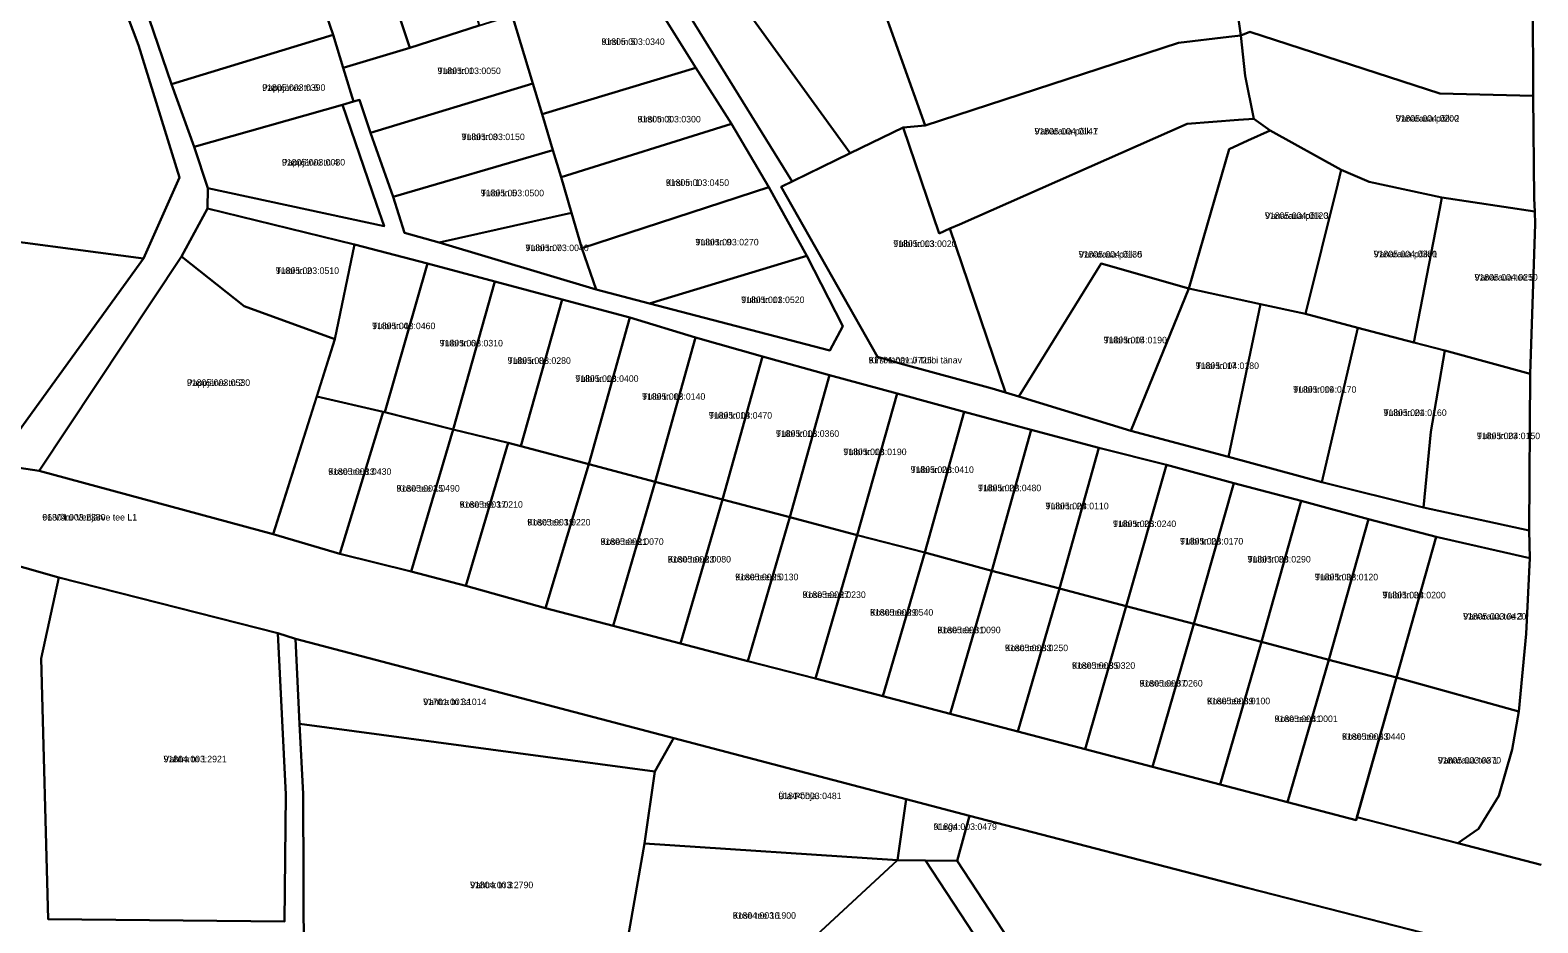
# Model space of a CAD drawing. Extents: x 655954 to 711923, y 6395079 to 6429745.
# Drawn here: x 680345.2 to 680691.2, y 6412086.7 to 6412291.4 of the extents above; entities that cross this region are included whole.
import ezdxf

# ---------------------------------------------------------------- set-up
doc = ezdxf.new("R2010")
doc.units = 0
for name, color, linetype in [('L_AADRESS', 7, 'Continuous'), ('PIIR', 7, 'Continuous'), ('TUNNUS', 7, 'Continuous')]:
    doc.layers.add(name, color=color, linetype=linetype)

msp = doc.modelspace()

# ---------------------------------------------------------------- linework, layer by layer
at = {"layer": 'PIIR'}
for points in [[(680691.94, 6412100.04), (680672.88, 6412104.96), (680677.62, 6412108.25), (680682.23, 6412115.86), (680685.31, 6412126.44), (680686.83, 6412135.18), (680688.5, 6412152.96), (680689.33, 6412170.32), (680689.19, 6412176.7), (680689.48, 6412212.64), (680690.62, 6412246.92), (680690.49, 6412249.87), (680690.36, 6412252.83), (680690.15, 6412276.38), (680690.04, 6412298.6), (680689.21, 6412320.29), (680688.26, 6412343.55), (680687.16, 6412365.36), (680684.23, 6412414.79), (680682.22, 6412435.76), (680657.8, 6412581.77), (680647.63, 6412619.14), (680636.79, 6412656.6), (680630.27, 6412681.69)], [(680468.27, 6412340.52), (680520.07, 6412256.74), (680517.59, 6412255.53), (680539.7, 6412216.49), (680544.84, 6412214.98), (680565.96, 6412209.26), (680569.03, 6412208.35), (680572.07, 6412207.45), (680597.84, 6412199.56), (680620.24, 6412193.6), (680641.67, 6412187.79), (680664.99, 6412181.96), (680689.19, 6412176.7), (680689.33, 6412170.32), (680667.84, 6412175.24), (680652.34, 6412179.26), (680636.92, 6412183.46), (680621.43, 6412187.52), (680606.01, 6412191.72), (680590.49, 6412195.64), (680574.95, 6412199.75), (680559.57, 6412203.92), (680544.16, 6412208.15), (680528.66, 6412212.34), (680513.3, 6412216.63), (680497.9, 6412220.95), (680482.82, 6412225.53), (680467.33, 6412229.65), (680451.85, 6412233.8), (680436.43, 6412237.95), (680419.64, 6412242.31), (680385.97, 6412250.53), (680386, 6412255.23), (680422.59, 6412247.31), (680426.51, 6412246.46), (680424.75, 6412251.56), (680416.9, 6412274.33), (680419.47, 6412275.06), (680420.82, 6412275.45), (680423.36, 6412267.88), (680428.53, 6412253.22), (680431.1, 6412244.93), (680439.08, 6412242.76), (680475.1, 6412232), (680487.39, 6412228.72), (680528.7, 6412218.01), (680531.74, 6412223.58), (680523.46, 6412239.68), (680514.72, 6412255.44), (680506.14, 6412269.96), (680498.01, 6412282.81), (680484.86, 6412303.92)], [(680372.55, 6412294.06), (680377.69, 6412279.06), (680382.91, 6412264.69), (680386, 6412255.23), (680385.97, 6412250.53), (680379.93, 6412239.55), (680347.28, 6412190.34), (680337.05, 6412191.89), (680371.24, 6412239.08), (680379.49, 6412257.67), (680370.12, 6412288.02), (680357.48, 6412321.49)], [(680705.81, 6412074.78), (680677.03, 6412081.28), (680624.53, 6412094.76), (680560.78, 6412111.23), (680546.23, 6412115.07), (680492.93, 6412129.05), (680406.11, 6412151.85), (680402.06, 6412153.11), (680351.83, 6412165.88), (680336.14, 6412170.36), (680242.17, 6412197.84), (680196.94, 6412209.71), (680171.26, 6412215.95), (680148.41, 6412221.98), (680121.74, 6412229.75), (680098.7, 6412238.99)], [(680337.05, 6412191.89), (680347.28, 6412190.34), (680400.99, 6412175.85), (680416.33, 6412171.33), (680432.63, 6412167.26), (680445.22, 6412163.97), (680463.53, 6412158.9), (680479, 6412154.86), (680494.47, 6412150.81), (680509.95, 6412146.76), (680525.42, 6412142.71), (680540.9, 6412138.67), (680556.38, 6412134.62), (680571.85, 6412130.57), (680587.32, 6412126.52), (680602.8, 6412122.48), (680618.27, 6412118.43), (680633.75, 6412114.38), (680649.5, 6412110.26), (680649.69, 6412110.94), (680672.88, 6412104.96), (680691.94, 6412100.04)], [(680340.18, 6412080.79), (680339.82, 6412121.56), (680338.98, 6412165.98), (680336.14, 6412170.36), (680351.83, 6412165.88), (680347.79, 6412147.37), (680349.36, 6412087.58), (680403.59, 6412086.99), (680403.88, 6412116.18), (680402.06, 6412153.11), (680406.11, 6412151.85), (680407.08, 6412132.37), (680407.88, 6412116.26), (680408.14, 6412056.92)]]:
    msp.add_lwpolyline(points, dxfattribs=at)
for points in [[(680468.27, 6412340.52), (680486.71, 6412324.31), (680504.21, 6412303.58), (680533.37, 6412263.23), (680520.07, 6412256.74)], [(680419.26, 6412326.61), (680436.31, 6412331.9), (680448.28, 6412292.55), (680432.38, 6412287.38)], [(680417.09, 6412282.78), (680414.79, 6412290.36), (680409.59, 6412305.53), (680404.56, 6412321.9), (680419.26, 6412326.61), (680432.38, 6412287.38)], [(680270.91, 6412285.97), (680269.56, 6412291.77), (680268.21, 6412300.15), (680272.04, 6412300.46), (680309.99, 6412309.75), (680357.48, 6412321.49), (680370.12, 6412288.02), (680379.49, 6412257.67), (680371.24, 6412239.08), (680328.42, 6412244.77), (680267.41, 6412253.09), (680266.95, 6412257.92), (680268.29, 6412258.95), (680268.5, 6412260.8), (680268.26, 6412264.21), (680268.94, 6412267.94), (680271.87, 6412272.08), (680272.87, 6412275.64), (680272.53, 6412278.95)], [(680618.32, 6412308.62), (680620.58, 6412307.34), (680623.03, 6412290.2), (680620.29, 6412289.89), (680608.75, 6412288.56), (680550.62, 6412269.6), (680539.47, 6412300.88), (680536.7, 6412308.12), (680581.04, 6412320.56), (680588.15, 6412306.97), (680590.63, 6412307.28)], [(680504.21, 6412303.58), (680533.53, 6412316.71), (680536.7, 6412308.12), (680539.47, 6412300.88), (680550.62, 6412269.6), (680545.58, 6412269.1), (680533.37, 6412263.23)], [(680377.69, 6412279.06), (680372.55, 6412294.06), (680409.59, 6412305.53), (680414.79, 6412290.36)], [(680667.16, 6412298.96), (680690.04, 6412298.6), (680690.15, 6412276.38), (680668.68, 6412276.91), (680625.09, 6412291.05), (680623.03, 6412290.2), (680620.58, 6412307.34), (680622.84, 6412306.06)], [(680498.01, 6412282.81), (680462.72, 6412272.18), (680460.59, 6412279.24), (680455.87, 6412294.86), (680463.42, 6412297.01), (680484.86, 6412303.92)], [(680420.82, 6412275.45), (680419.47, 6412275.06), (680417.09, 6412282.78), (680432.38, 6412287.38), (680448.28, 6412292.55), (680455.87, 6412294.86), (680460.59, 6412279.24), (680423.36, 6412267.88)], [(680625.09, 6412291.05), (680668.68, 6412276.91), (680690.15, 6412276.38), (680690.36, 6412252.83), (680690.49, 6412249.87), (680669.19, 6412253.04), (680652.49, 6412256.69), (680646.06, 6412259.42), (680629.76, 6412268.41), (680626.03, 6412271.13), (680624.08, 6412280.94), (680623.03, 6412290.2)], [(680414.79, 6412290.36), (680417.09, 6412282.78), (680419.47, 6412275.06), (680416.9, 6412274.33), (680382.91, 6412264.69), (680377.69, 6412279.06)], [(680553.84, 6412244.84), (680545.58, 6412269.1), (680550.62, 6412269.6), (680608.75, 6412288.56), (680620.3, 6412289.88), (680623.03, 6412290.2), (680624.08, 6412280.94), (680626.03, 6412271.13), (680622.48, 6412270.85), (680610.75, 6412269.93), (680558.47, 6412246.88), (680556.28, 6412245.92)], [(680498.01, 6412282.81), (680506.14, 6412269.96), (680467.07, 6412257.75), (680465.21, 6412263.92), (680462.72, 6412272.18)], [(680460.59, 6412279.24), (680462.72, 6412272.18), (680465.21, 6412263.92), (680428.53, 6412253.22), (680423.36, 6412267.88)], [(680382.91, 6412264.69), (680416.9, 6412274.33), (680424.75, 6412251.56), (680426.51, 6412246.46), (680422.59, 6412247.31), (680386, 6412255.23)], [(680626.03, 6412271.13), (680629.76, 6412268.41), (680624.68, 6412266.13), (680620.36, 6412264.18), (680611.12, 6412232.19), (680590.98, 6412237.95), (680572.07, 6412207.45), (680569.03, 6412208.35), (680556.28, 6412245.92), (680558.47, 6412246.88), (680610.75, 6412269.93), (680622.48, 6412270.85)], [(680506.14, 6412269.96), (680514.72, 6412255.44), (680471.82, 6412241.48), (680469.46, 6412249.54), (680467.07, 6412257.75)], [(680553.84, 6412244.84), (680556.28, 6412245.92), (680569.03, 6412208.35), (680565.96, 6412209.26), (680544.84, 6412214.98), (680539.7, 6412216.49), (680517.59, 6412255.53), (680533.37, 6412263.23), (680545.58, 6412269.1)], [(680629.76, 6412268.41), (680646.06, 6412259.42), (680645.27, 6412256.23), (680637.89, 6412226.37), (680627.58, 6412228.64), (680611.12, 6412232.19), (680620.36, 6412264.18), (680624.68, 6412266.13)], [(680465.21, 6412263.92), (680467.07, 6412257.75), (680469.46, 6412249.54), (680439.08, 6412242.76), (680431.1, 6412244.93), (680428.53, 6412253.22)], [(680266.95, 6412257.92), (680267.41, 6412253.09), (680328.42, 6412244.77), (680371.24, 6412239.08), (680337.05, 6412191.89), (680190.32, 6412232.69), (680191.57, 6412236.5), (680194.23, 6412244.67), (680196.86, 6412252.6), (680212.46, 6412248.67), (680230.28, 6412253.54), (680253.6, 6412257.24), (680261.5, 6412255.76)], [(680668.71, 6412250.56), (680662.72, 6412219.81), (680649.9, 6412223.21), (680637.89, 6412226.37), (680645.27, 6412256.23), (680646.06, 6412259.42), (680652.49, 6412256.69), (680669.19, 6412253.04)], [(680514.72, 6412255.44), (680523.46, 6412239.68), (680487.39, 6412228.72), (680475.1, 6412232), (680471.82, 6412241.48)], [(680669.19, 6412253.04), (680690.49, 6412249.87), (680690.62, 6412246.92), (680689.48, 6412212.64), (680669.89, 6412217.97), (680662.73, 6412219.81), (680668.71, 6412250.56)], [(680394.31, 6412228.15), (680379.93, 6412239.55), (680385.97, 6412250.53), (680419.64, 6412242.31), (680415.16, 6412220.56)], [(680469.46, 6412249.54), (680471.82, 6412241.48), (680475.1, 6412232), (680439.08, 6412242.76)], [(680379.93, 6412239.55), (680394.31, 6412228.15), (680415.15, 6412220.55), (680400.99, 6412175.85), (680347.28, 6412190.34)], [(680426.26, 6412203.91), (680411, 6412207.4), (680415.16, 6412220.56), (680419.64, 6412242.31), (680436.43, 6412237.95), (680426.59, 6412203.83)], [(680523.46, 6412239.68), (680531.74, 6412223.58), (680528.7, 6412218.01), (680487.39, 6412228.72)], [(680442.29, 6412199.83), (680426.59, 6412203.83), (680436.43, 6412237.95), (680451.85, 6412233.8)], [(680572.07, 6412207.45), (680590.98, 6412237.95), (680611.12, 6412232.19), (680597.84, 6412199.56)], [(680467.33, 6412229.65), (680457.86, 6412196.01), (680454.95, 6412196.78), (680442.29, 6412199.83), (680451.85, 6412233.8)], [(680597.84, 6412199.56), (680611.12, 6412232.19), (680627.58, 6412228.64), (680620.24, 6412193.6)], [(680473.43, 6412191.9), (680457.86, 6412196.01), (680467.33, 6412229.65), (680482.82, 6412225.53)], [(680488.69, 6412187.87), (680473.43, 6412191.9), (680482.82, 6412225.53), (680497.9, 6412220.95)], [(680620.24, 6412193.6), (680627.58, 6412228.64), (680637.89, 6412226.37), (680649.9, 6412223.21), (680641.67, 6412187.79)], [(680641.67, 6412187.79), (680649.9, 6412223.21), (680662.72, 6412219.81), (680669.89, 6412217.97), (680666.68, 6412199.35), (680664.99, 6412181.96)], [(680497.9, 6412220.95), (680513.3, 6412216.63), (680504.09, 6412183.81), (680488.69, 6412187.87)], [(680513.3, 6412216.63), (680528.66, 6412212.34), (680519.55, 6412179.73), (680504.09, 6412183.81)], [(680666.68, 6412199.35), (680669.89, 6412217.97), (680689.48, 6412212.64), (680689.19, 6412176.7), (680664.99, 6412181.96)], [(680544.16, 6412208.15), (680535.01, 6412175.64), (680519.55, 6412179.73), (680528.66, 6412212.34)], [(680544.16, 6412208.15), (680559.57, 6412203.92), (680550.52, 6412171.66), (680535.01, 6412175.64)], [(680411, 6412207.4), (680426.26, 6412203.91), (680416.33, 6412171.33), (680400.99, 6412175.85)], [(680426.26, 6412203.91), (680442.29, 6412199.83), (680432.63, 6412167.26), (680416.33, 6412171.33)], [(680574.95, 6412199.75), (680565.95, 6412167.47), (680550.52, 6412171.66), (680559.57, 6412203.92)], [(680442.29, 6412199.83), (680454.95, 6412196.78), (680445.22, 6412163.97), (680432.63, 6412167.26)], [(680590.49, 6412195.64), (680581.44, 6412163.39), (680565.95, 6412167.47), (680574.95, 6412199.75)], [(680454.95, 6412196.78), (680457.86, 6412196.01), (680473.43, 6412191.9), (680463.53, 6412158.9), (680445.22, 6412163.97)], [(680590.49, 6412195.64), (680606.01, 6412191.72), (680596.77, 6412159.33), (680581.44, 6412163.39)], [(680473.43, 6412191.9), (680488.69, 6412187.87), (680479, 6412154.86), (680463.53, 6412158.9)], [(680606.01, 6412191.72), (680621.43, 6412187.52), (680612.25, 6412155.26), (680596.77, 6412159.33)], [(680488.69, 6412187.87), (680504.09, 6412183.81), (680494.47, 6412150.81), (680479, 6412154.86)], [(680636.92, 6412183.46), (680627.76, 6412151.16), (680612.25, 6412155.26), (680621.43, 6412187.52)], [(680504.09, 6412183.81), (680519.55, 6412179.73), (680509.95, 6412146.76), (680494.47, 6412150.81)], [(680636.92, 6412183.46), (680652.34, 6412179.26), (680643.28, 6412147.06), (680627.76, 6412151.16)], [(680519.55, 6412179.73), (680535.01, 6412175.64), (680525.42, 6412142.71), (680509.95, 6412146.76)], [(680652.34, 6412179.26), (680667.84, 6412175.24), (680658.78, 6412142.98), (680643.28, 6412147.06)], [(680535.01, 6412175.64), (680550.52, 6412171.66), (680540.9, 6412138.67), (680525.42, 6412142.71)], [(680689.33, 6412170.32), (680688.5, 6412152.96), (680686.83, 6412135.18), (680658.78, 6412142.98), (680667.84, 6412175.24)], [(680550.52, 6412171.66), (680565.95, 6412167.47), (680556.38, 6412134.62), (680540.9, 6412138.67)], [(680565.95, 6412167.47), (680581.44, 6412163.39), (680571.85, 6412130.57), (680556.38, 6412134.62)], [(680347.79, 6412147.37), (680351.83, 6412165.88), (680402.06, 6412153.11), (680403.88, 6412116.18), (680403.59, 6412086.99), (680349.36, 6412087.58)], [(680581.44, 6412163.39), (680596.77, 6412159.33), (680587.32, 6412126.52), (680571.85, 6412130.57)], [(680596.77, 6412159.33), (680612.25, 6412155.26), (680602.8, 6412122.48), (680587.32, 6412126.52)], [(680612.25, 6412155.26), (680627.76, 6412151.16), (680618.27, 6412118.43), (680602.8, 6412122.48)], [(680492.67, 6412128.6), (680488.61, 6412121.45), (680407.08, 6412132.37), (680406.11, 6412151.85), (680492.93, 6412129.05)], [(680627.76, 6412151.16), (680643.28, 6412147.06), (680633.75, 6412114.38), (680618.27, 6412118.43)], [(680643.28, 6412147.06), (680658.78, 6412142.98), (680649.5, 6412110.26), (680633.75, 6412114.38)], [(680685.31, 6412126.44), (680682.23, 6412115.86), (680677.62, 6412108.25), (680672.88, 6412104.96), (680649.69, 6412110.94), (680658.78, 6412142.98), (680686.83, 6412135.18)], [(680431.81, 6412061.43), (680408.14, 6412056.92), (680407.88, 6412116.26), (680407.08, 6412132.37), (680488.61, 6412121.45), (680486.18, 6412104.9), (680481.38, 6412077.45), (680480.42, 6412070.77)], [(680492.67, 6412128.6), (680492.93, 6412129.05), (680546.23, 6412115.07), (680544.25, 6412101.11), (680486.18, 6412104.9), (680488.61, 6412121.45)], [(680546.23, 6412115.07), (680560.78, 6412111.23), (680557.95, 6412100.96), (680550.71, 6412101.04), (680544.25, 6412101.11)], [(680677.03, 6412081.28), (680685.71, 6412071.64), (680689.23, 6412054.08), (680672.6, 6412046.64), (680620.2, 6412023.18), (680611.8, 6412018.81), (680557.95, 6412100.96), (680560.78, 6412111.23), (680624.53, 6412094.76)], [(680486.18, 6412104.9), (680544.25, 6412101.11), (680511.18, 6412070.4), (680481.38, 6412077.45)], [(680544.25, 6412101.11), (680550.71, 6412101.04), (680580.77, 6412055.2), (680552.21, 6412022.55), (680551.29, 6412021.49), (680549.92, 6412023.92), (680548.09, 6412023.97), (680546.58, 6412025.26), (680546.91, 6412029.19), (680546.21, 6412031.37), (680544.02, 6412034.93), (680542.63, 6412038.58), (680538.09, 6412047.02), (680530.02, 6412054.64), (680526.3, 6412058.97), (680512.15, 6412067.76), (680509.19, 6412068.44), (680511.18, 6412070.4)], [(680550.71, 6412101.04), (680557.95, 6412100.96), (680611.8, 6412018.81), (680604.05, 6411974.9), (680595.49, 6411963.69), (680594.02, 6411961.84), (680593.2, 6411962.5), (680587.62, 6411966.99), (680576.7, 6411973.66), (680569.05, 6411980.7), (680563.1, 6411989.19), (680554.25, 6411997.32), (680549.63, 6412001.81), (680548.91, 6412006.67), (680550.97, 6412010.91), (680551.94, 6412015.4), (680551.43, 6412021.22), (680551.29, 6412021.49), (680552.21, 6412022.55), (680580.77, 6412055.2)]]:
    msp.add_lwpolyline(points, close=True, dxfattribs=at)

# ---------------------------------------------------------------- texts
at = {"layer": 'L_AADRESS'}
for s, p in [('Kirsi tn 5', (680476.34, 6412288.05)), ('Tulbi tn 1', (680438.74, 6412281.37)), ('Pappjärve tn 6', (680398.48, 6412277.53)), ('Kirsi tn 3', (680484.62, 6412270.28)), ('Vanaraua põik 2', (680658.58, 6412270.46)), ('Tulbi tn 3', (680444.23, 6412266.23)), ('Vanaraua põik 7', (680575.7, 6412267.52)), ('Pappjärve tn 4', (680403.01, 6412260.4)), ('Kirsi tn 1', (680491.11, 6412255.72)), ('Tulbi tn 5', (680448.65, 6412253.34)), ('Vanaraua põik 3', (680628.59, 6412248.15)), ('Tulbi tn 9', (680497.9, 6412242.08)), ('Tulbi tn 13', (680543.31, 6412241.72)), ('Tulbi tn 7', (680458.9, 6412240.77)), ('Vanaraua põik 5', (680585.85, 6412239.29)), ('Vanaraua põik 1', (680653.54, 6412239.35)), ('Tulbi tn 2', (680401.61, 6412235.54)), ('Vanaraua tee 5', (680676.67, 6412234.02)), ('Tulbi tn 11', (680508.42, 6412228.85)), ('Tulbi tn 4', (680423.71, 6412222.87)), ('Tulbi tn 6', (680439.22, 6412218.91)), ('Tulbi tn 15', (680591.59, 6412219.62)), ('Tulbi tn 8', (680454.81, 6412214.91)), ('Kirsi tänav // Tulbi tänav', (680537.65, 6412215.01)), ('Tulbi tn 17', (680612.71, 6412213.73)), ('Pappjärve tn 2', (680381.21, 6412209.86)), ('Tulbi tn 10', (680470.34, 6412210.78)), ('Tulbi tn 12', (680485.66, 6412206.67)), ('Tulbi tn 19', (680635.07, 6412208.29)), ('Tulbi tn 21', (680655.78, 6412202.96)), ('Tulbi tn 14', (680500.99, 6412202.35)), ('Tulbi tn 16', (680516.38, 6412198.17)), ('Tulbi tn 23', (680677.23, 6412197.64)), ('Tulbi tn 18', (680531.85, 6412193.98)), ('Kose tee 13', (680413.62, 6412189.46)), ('Tulbi tn 20', (680547.29, 6412189.89)), ('Tulbi tn 22', (680562.74, 6412185.7)), ('Kose tee 15', (680429.31, 6412185.61)), ('66 Võru-Verijärve tee L1', (680348.03, 6412178.98)), ('Kose tee 17', (680443.79, 6412181.91)), ('Tulbi tn 24', (680578.22, 6412181.56)), ('Kose tee 19', (680459.32, 6412177.84)), ('Tulbi tn 26', (680593.72, 6412177.48)), ('Kose tee 21', (680476.11, 6412173.4)), ('Tulbi tn 28', (680609.1, 6412173.48)), ('Kose tee 23', (680491.55, 6412169.35)), ('Tulbi tn 30', (680624.59, 6412169.35)), ('Kose tee 25', (680507.01, 6412165.28)), ('Tulbi tn 32', (680640.05, 6412165.26)), ('Kose tee 27', (680522.48, 6412161.22)), ('Tulbi tn 34', (680655.56, 6412161.13)), ('Kose tee 29', (680537.97, 6412157.16)), ('Vanaraua tee 3', (680674.05, 6412156.27)), ('Kose tee 31', (680553.43, 6412153.13)), ('Kose tee 33', (680568.91, 6412149.02)), ('Kose tee 35', (680584.31, 6412144.97)), ('Kose tee 37', (680599.79, 6412140.9)), ('Vahtra tn 3a', (680435.43, 6412136.65)), ('Kose tee 39', (680615.28, 6412136.84)), ('Kose tee 41', (680630.78, 6412132.76)), ('Kose tee 43', (680646.27, 6412128.69)), ('Vahtra tn 1', (680375.84, 6412123.53)), ('Vanaraua tee 1', (680668.26, 6412123.25)), ('Üla-Põhja', (680516.93, 6412115.08)), ('Nurga', (680552.56, 6412108.02)), ('Vahtra tn 3', (680446.18, 6412094.65)), ('Kose tee 16', (680506.46, 6412087.65))]:
    msp.add_text(s, height=1.5, dxfattribs=at).set_placement(p)
at = {"layer": 'TUNNUS'}
for s, p in [('91805:003:0340', (680476.34, 6412288.05)), ('91805:003:0050', (680438.74, 6412281.37)), ('91805:003:0390', (680398.48, 6412277.53)), ('91805:003:0300', (680484.62, 6412270.28)), ('91805:004:0200', (680658.58, 6412270.46)), ('91805:003:0150', (680444.23, 6412266.23)), ('91805:004:0141', (680575.7, 6412267.52)), ('91805:003:0030', (680403.01, 6412260.4)), ('91805:003:0450', (680491.11, 6412255.72)), ('91805:003:0500', (680448.65, 6412253.34)), ('91805:004:0120', (680628.59, 6412248.15)), ('91805:003:0270', (680497.9, 6412242.08)), ('91805:003:0020', (680543.31, 6412241.72)), ('91805:003:0040', (680458.9, 6412240.77)), ('91805:004:0130', (680585.85, 6412239.29)), ('91805:004:0380', (680653.54, 6412239.35)), ('91805:003:0510', (680401.61, 6412235.54)), ('91805:004:0250', (680676.67, 6412234.02)), ('91805:003:0520', (680508.42, 6412228.85)), ('91805:003:0460', (680423.71, 6412222.87)), ('91805:003:0310', (680439.22, 6412218.91)), ('91805:004:0190', (680591.59, 6412219.62)), ('91805:003:0280', (680454.81, 6412214.91)), ('91701:001:0725', (680537.65, 6412215.01)), ('91805:004:0180', (680612.71, 6412213.73)), ('91805:003:0530', (680381.21, 6412209.86)), ('91805:003:0400', (680470.34, 6412210.78)), ('91805:003:0140', (680485.66, 6412206.67)), ('91805:004:0170', (680635.07, 6412208.29)), ('91805:004:0160', (680655.78, 6412202.96)), ('91805:003:0470', (680500.99, 6412202.35)), ('91805:003:0360', (680516.38, 6412198.17)), ('91805:004:0150', (680677.23, 6412197.64)), ('91805:003:0190', (680531.85, 6412193.98)), ('91805:003:0430', (680413.62, 6412189.46)), ('91805:003:0410', (680547.29, 6412189.89)), ('91805:003:0480', (680562.74, 6412185.7)), ('91805:003:0490', (680429.31, 6412185.61)), ('91804:003:2380', (680348.03, 6412178.98)), ('91805:003:0210', (680443.79, 6412181.91)), ('91805:003:0110', (680578.22, 6412181.56)), ('91805:003:0220', (680459.32, 6412177.84)), ('91805:003:0240', (680593.72, 6412177.48)), ('91805:003:0070', (680476.11, 6412173.4)), ('91805:003:0170', (680609.1, 6412173.48)), ('91805:003:0080', (680491.55, 6412169.35)), ('91805:003:0290', (680624.59, 6412169.35)), ('91805:003:0130', (680507.01, 6412165.28)), ('91805:003:0120', (680640.05, 6412165.26)), ('91805:003:0230', (680522.48, 6412161.22)), ('91805:003:0200', (680655.56, 6412161.13)), ('91805:003:0540', (680537.97, 6412157.16)), ('91805:003:0420', (680674.05, 6412156.27)), ('91805:003:0090', (680553.43, 6412153.13)), ('91805:003:0250', (680568.91, 6412149.02)), ('91805:003:0320', (680584.31, 6412144.97)), ('91805:003:0260', (680599.79, 6412140.9)), ('91701:001:1014', (680435.43, 6412136.65)), ('91805:003:0100', (680615.28, 6412136.84)), ('91805:003:0001', (680630.78, 6412132.76)), ('91805:003:0440', (680646.27, 6412128.69)), ('91804:003:2921', (680375.84, 6412123.53)), ('91805:003:0370', (680668.26, 6412123.25)), ('91804:003:0481', (680516.93, 6412115.08)), ('91804:003:0479', (680552.56, 6412108.02)), ('91804:003:2790', (680446.18, 6412094.65)), ('91804:003:1900', (680506.46, 6412087.65))]:
    msp.add_text(s, height=1.5, dxfattribs=at).set_placement(p)

doc.saveas('drawing.dxf')
